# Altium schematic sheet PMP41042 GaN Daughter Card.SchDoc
size 431 x 279 mm; PageSetup: Record=PageOptions¦CenterHorizontal=True¦CenterVertical=True¦PrintScale=1.00¦XCorrection=1.00¦YCorrection=1.00¦PrintKind=0¦BorderSize=5000000¦LeftOffset=0¦BottomOffset=0¦Orientation=2¦PaperLength=1000¦PaperWidth=1000¦Scale=100¦PaperSource=15¦PrintQuality=600¦MediaType=1¦DitherType=10¦PaperKind=Letter¦PrintScaleMode=1
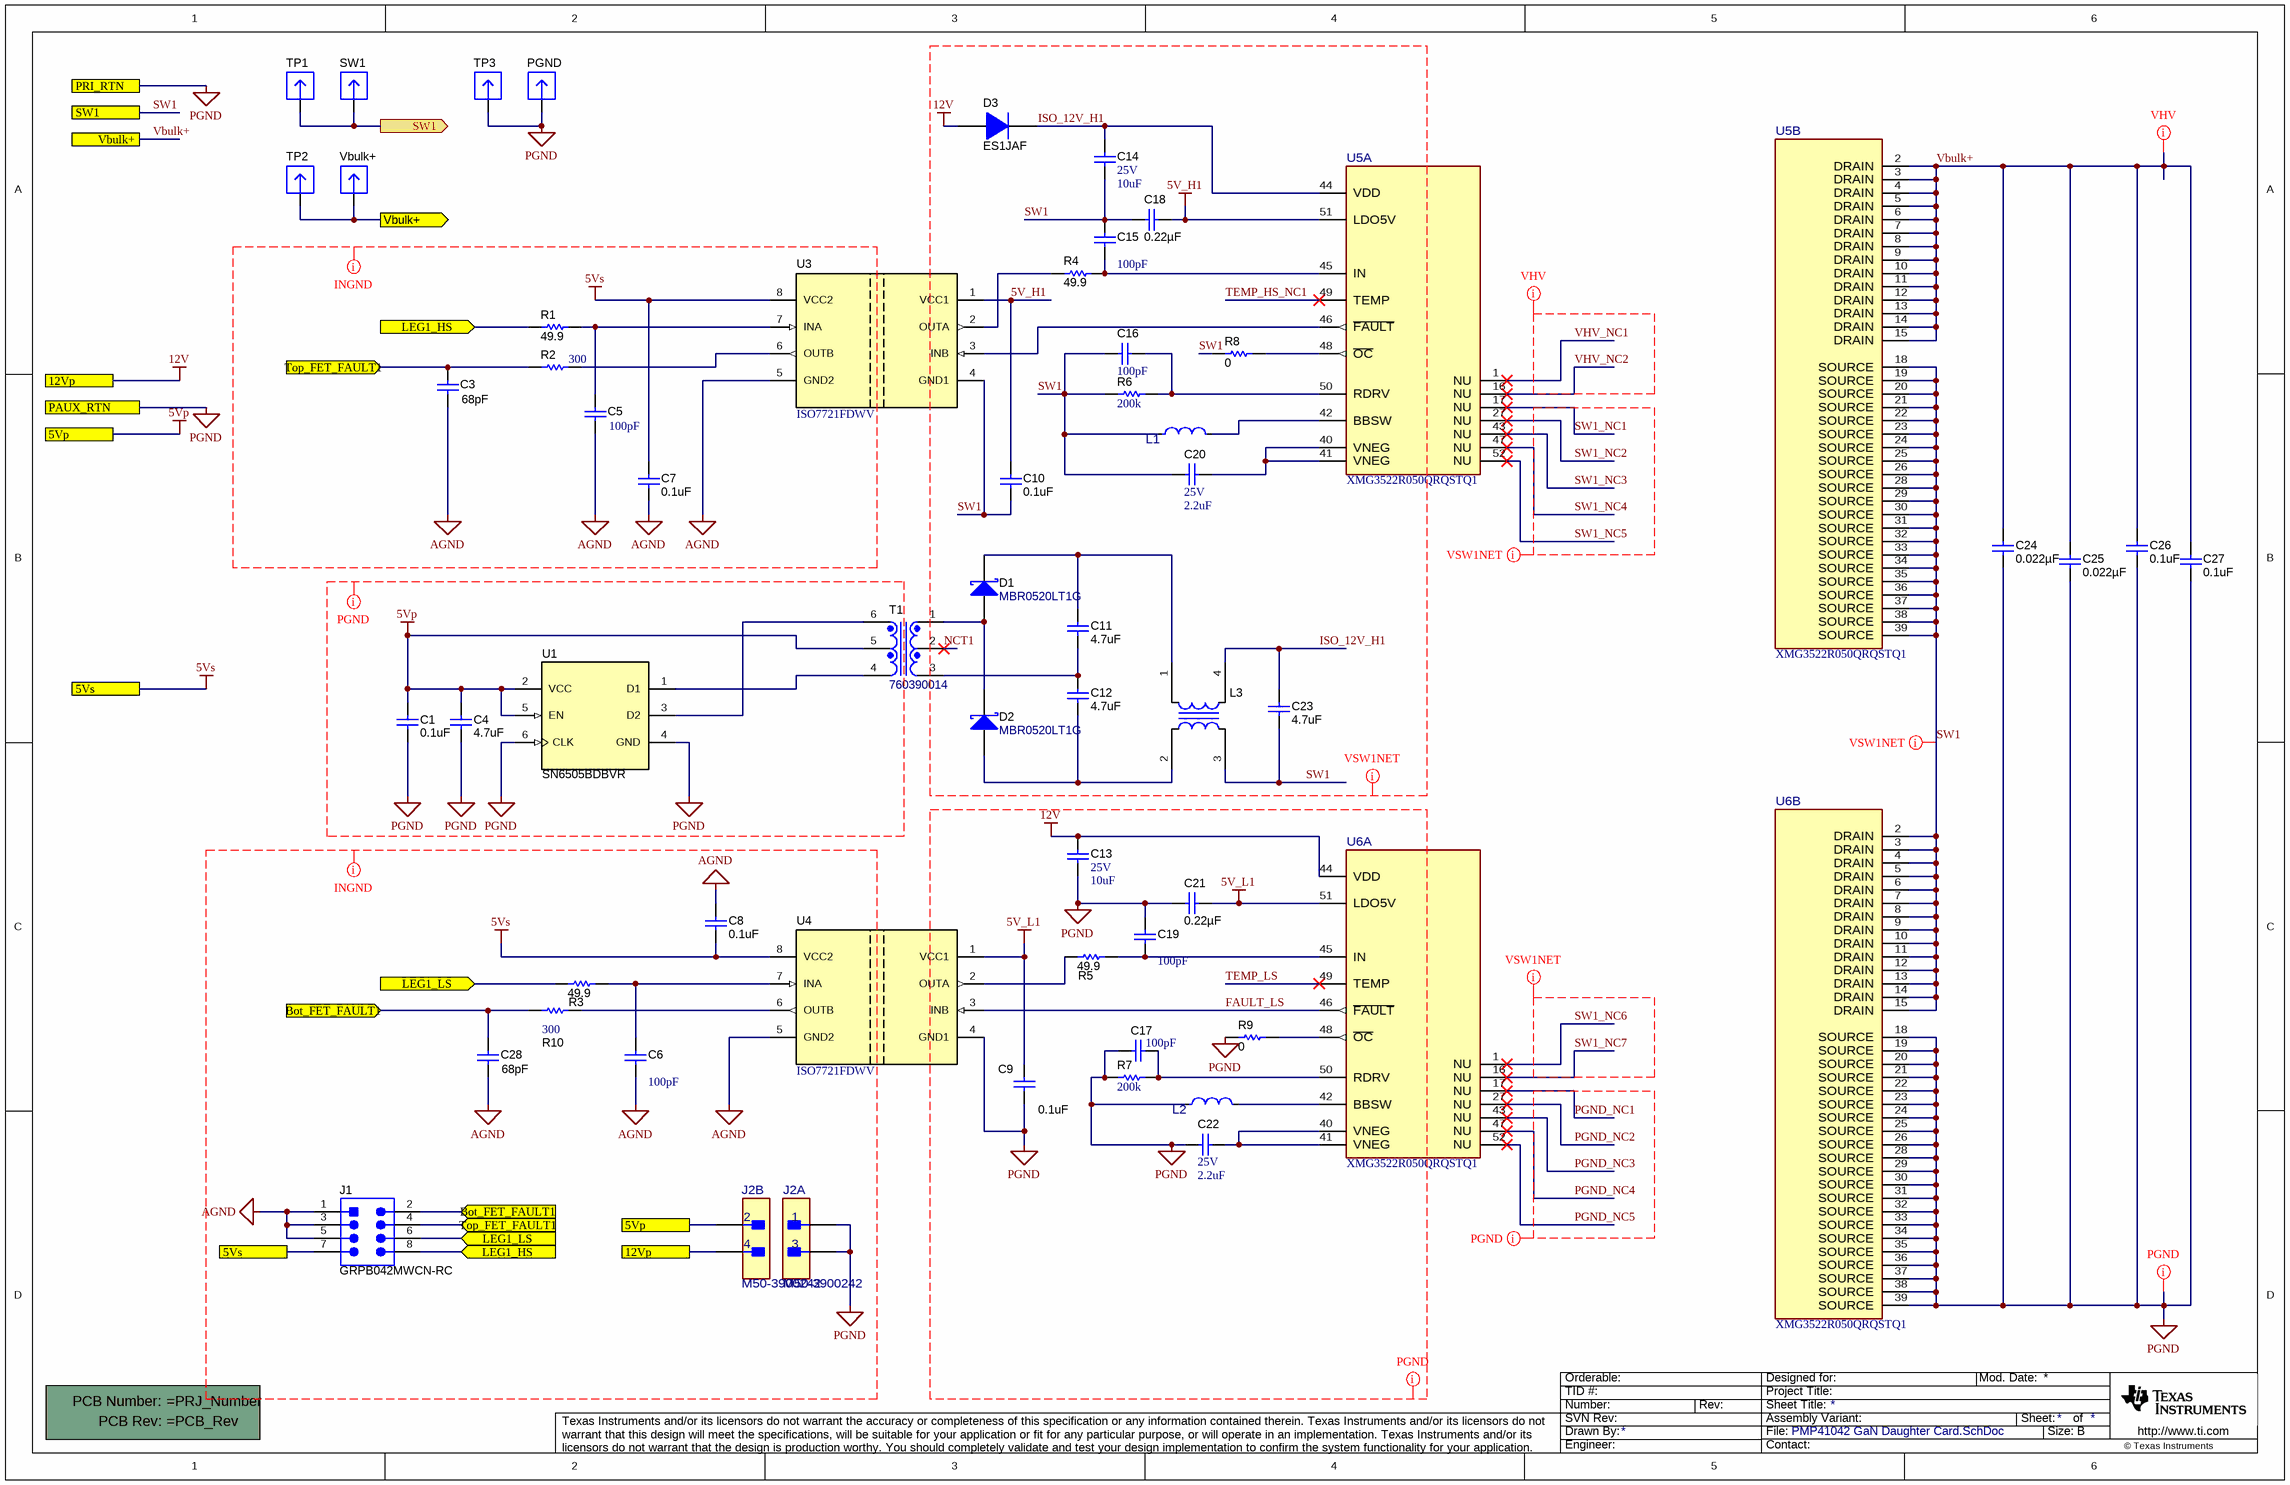
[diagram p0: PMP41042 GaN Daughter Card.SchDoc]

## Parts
!PCB1  Printed Circuit Board  (value not drawn)  (mechanical)
C1  ValueDisplayed: 0.1uF  [0402]  (hidden comment: C1005X7R1H104K050BB)
C3  ValueDisplayed: 68pF  [0402L]  (hidden comment: C1005C0G1H680J050BA)
C4  ValueDisplayed: 4.7uF  [0805_HV]  (hidden comment: GCM21BR71C475KA73L)
C5  ValueDisplayed: 100pF  [0402L]  (hidden comment: 04025A101FAT2A)
C6  ValueDisplayed: 100pF  [0402L]  (hidden comment: 04025A101FAT2A)
C7  ValueDisplayed: 0.1uF  [0402L]  (hidden comment: C1005X7R1H104K050BB)
C8  ValueDisplayed: 0.1uF  [0402L]  (hidden comment: C1005X7R1H104K050BB)
C9  ValueDisplayed: 0.1uF  [0402L]  (hidden comment: C1005X7R1H104K050BB)
C10  ValueDisplayed: 0.1uF  [0402L]  (hidden comment: C1005X7R1H104K050BB)
C11  ValueDisplayed: 4.7uF  [0603]  (hidden comment: C1608X5R1V475K080AC)
C12  ValueDisplayed: 4.7uF  [0603]  (hidden comment: C1608X5R1V475K080AC)
C13  VDC_V: 25V  ValueDisplayed: 10uF  [1206_190]  (hidden comment: C3216X7R1E106M160AE)
C14  VDC_V: 25V  ValueDisplayed: 10uF  [1206_190]  (hidden comment: C3216X7R1E106M160AE)
C15  ValueDisplayed: 100pF  [0402L]  (hidden comment: 04025A101FAT2A)
C16  ValueDisplayed: 100pF  [0402L]  (hidden comment: 04025A101FAT2A)
C17  ValueDisplayed: 100pF  [0402L]  (hidden comment: 04025A101FAT2A)
C18  ValueDisplayed: 0.22µF  [0402L]  (hidden comment: CL05B224KO5NNNC)
C19  ValueDisplayed: 100pF  [0402L]  (hidden comment: 04025A101FAT2A)
C20  VDC_V: 25V  ValueDisplayed: 2.2uF  [0402L]  (hidden comment: GRT155R61E225KE13D)
C21  ValueDisplayed: 0.22µF  [0402L]  (hidden comment: CL05B224KO5NNNC)
C22  VDC_V: 25V  ValueDisplayed: 2.2uF  [0402L]  (hidden comment: GRT155R61E225KE13D)
C23  ValueDisplayed: 4.7uF  [0603]  (hidden comment: C1608X5R1V475K080AC)
C24  ValueDisplayed: 0.022µF  [1206_190]  (hidden comment: C1206C223KDRACTU)
C25  ValueDisplayed: 0.022µF  [1206_190]  (hidden comment: C1206C223KDRACTU)
C26  ValueDisplayed: 0.1uF  [1812_254]  (hidden comment: C1812W104KDRACTU)
C27  ValueDisplayed: 0.1uF  [1812_254]  (hidden comment: C1812W104KDRACTU)
C28  ValueDisplayed: 68pF  [0402L]  (hidden comment: C1005C0G1H680J050BA)
D1  MBR0520LT1G  [SOD-123]
D2  MBR0520LT1G  [SOD-123]
D3  ES1JAF  [SMAF]
J1  GRPB042MWCN-RC  [Sullins_GRPB042MWCN]
J2  M50-3900242  [FP-M50-3900242_HDR4-MFG]  (parts A,B of 2)
L1  SDEM20161T-4R7MS  [FP-SDEM20161T-4R7MS_SMD2-MFG]  (value not drawn)
L2  SDEM20161T-4R7MS  [FP-SDEM20161T-4R7MS_SMD2-MFG]  (value not drawn)
L3  ACM2520-601-2P-T002  [TDK_ACM2520-2P]  (value not drawn)
PGND  3621-0-32-15-00-00-08-0  [Mill-Max_3621-0-32-xx-00-00-08-0]  (value not drawn)
R1  ValueDisplayed: 49.9  [0402L]  (hidden comment: RC0402FR-0749R9L)
R2  ValueDisplayed: 300  [0402L]  (hidden comment: CRCW0402300RJNED)
R3  ValueDisplayed: 49.9  [0402L]  (hidden comment: RC0402FR-0749R9L)
R4  ValueDisplayed: 49.9  [0402L]  (hidden comment: RC0402FR-0749R9L)
R5  ValueDisplayed: 49.9  [0402L]  (hidden comment: RC0402FR-0749R9L)
R6  ValueDisplayed: 200k  [0402L]  (hidden comment: ERJ-2RKF2003X)
R7  ValueDisplayed: 200k  [0402L]  (hidden comment: ERJ-2RKF2003X)
R8  ValueDisplayed: 0  [0402L]  (hidden comment: ERJ-2GE0R00X)  (no BOM)
R9  ValueDisplayed: 0  [0402L]  (hidden comment: ERJ-2GE0R00X)  (no BOM)
R10  ValueDisplayed: 300  [0402L]  (hidden comment: CRCW0402300RJNED)
SW1  3621-0-32-15-00-00-08-0  [Mill-Max_3621-0-32-xx-00-00-08-0]  (value not drawn)
T1  760390014  [Wurth_760390013]
TP1  3621-0-32-15-00-00-08-0  [Mill-Max_3621-0-32-xx-00-00-08-0]  (value not drawn)
TP2  3621-0-32-15-00-00-08-0  [Mill-Max_3621-0-32-xx-00-00-08-0]  (value not drawn)
TP3  3621-0-32-15-00-00-08-0  [Mill-Max_3621-0-32-xx-00-00-08-0]  (value not drawn)
U1  SN6505BDBVR  [DBV0006A_N]
U3  ISO7721FDWV  [DWV0008A]
U4  ISO7721FDWV  [DWV0008A]
U5  PartNumber: XMG3522R050QRQSTQ1  [RQS0052A-MFG]  (hidden comment: XMG3522R030QRQSTQ1)  (parts A,B of 2)
U6  PartNumber: XMG3522R050QRQSTQ1  [RQS0052A-MFG]  (hidden comment: XMG3522R030QRQSTQ1)  (parts A,B of 2)
Vbulk+  3621-0-32-15-00-00-08-0  [Mill-Max_3621-0-32-xx-00-00-08-0]  (value not drawn)

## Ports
5Vp, 5Vs, 12Vp, Bot_FET_FAULT1 (in), LEG1_HS (in), LEG1_LS (in), PAUX_RTN, PRI_RTN, SW1, SW1 (out), Top_FET_FAULT1 (in), Vbulk+, Vbulk+ (out)

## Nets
5V_H1: C10.1 C18.2 U3.1(VCC1) U5.51(LDO5V)
5V_L1: C9.2 C21.2 U4.1(VCC1) U6.51(LDO5V)
5Vp: C1.1 C4.1 J2.2 T1.5 U1.2(VCC) U1.5(EN) ; port 5Vp
5Vs: C7.1 C8.2 J1.7 U3.8(VCC2) U4.8(VCC2) ; port 5Vs
12V: C13.1 D3.2(A) J2.4 U6.44(VDD) ; port 12Vp
AGND: C3.2 C5.2 C6.2 C7.2 C8.1 C28.2 J1.1 J1.3 J1.5 U3.5(GND2) U4.5(GND2)
PGND: C1.2 C4.2 C9.1 C13.2 C17.1 C19.1 C21.1 C22.2 C24.2 C25.2 C26.2 C27.2 J2.1 J2.3 L2.1 PGND.1 R7.1 R9.1 TP3.1 U1.4(GND) U1.6(CLK) U4.4(GND1) U6.18(SOURCE) U6.19(SOURCE) U6.20(SOURCE) U6.21(SOURCE) U6.22(SOURCE) U6.23(SOURCE) U6.24(SOURCE) U6.25(SOURCE) U6.26(SOURCE) U6.28(SOURCE) U6.29(SOURCE) U6.30(SOURCE) U6.31(SOURCE) U6.32(SOURCE) U6.33(SOURCE) U6.34(SOURCE) U6.35(SOURCE) U6.36(SOURCE) U6.37(SOURCE) U6.38(SOURCE) U6.39(SOURCE) ; port PRI_RTN, port PAUX_RTN
Bot_FET_FAULT1: C28.1 J1.2 R10.1 ; port Bot_FET_FAULT1
FAULT_LS: U4.3(INB) U6.46(~{FAULT})
ISO_12V_H1: C14.1 C23.1 D3.1(K) L3.4 U5.44(VDD)
LEG1_HS: J1.8 R1.1 ; port LEG1_HS
LEG1_LS: J1.6 R3.1 ; port LEG1_LS
NCT1: T1.2
PGND_NC1: U6.17(NU)
PGND_NC2: U6.27(NU)
PGND_NC3: U6.43(NU)
PGND_NC4: U6.47(NU)
PGND_NC5: U6.52(NU)
SW1: C10.2 C14.2 C15.1 C16.1 C18.1 C20.2 C23.2 L1.1 L3.3 R6.1 R8.1 SW1.1 TP1.1 U3.4(GND1) U5.18(SOURCE) U5.19(SOURCE) U5.20(SOURCE) U5.21(SOURCE) U5.22(SOURCE) U5.23(SOURCE) U5.24(SOURCE) U5.25(SOURCE) U5.26(SOURCE) U5.28(SOURCE) U5.29(SOURCE) U5.30(SOURCE) U5.31(SOURCE) U5.32(SOURCE) U5.33(SOURCE) U5.34(SOURCE) U5.35(SOURCE) U5.36(SOURCE) U5.37(SOURCE) U5.38(SOURCE) U5.39(SOURCE) U6.2(DRAIN) U6.3(DRAIN) U6.4(DRAIN) U6.5(DRAIN) U6.6(DRAIN) U6.7(DRAIN) U6.8(DRAIN) U6.9(DRAIN) U6.10(DRAIN) U6.11(DRAIN) U6.12(DRAIN) U6.13(DRAIN) U6.14(DRAIN) U6.15(DRAIN) ; port SW1
SW1_NC1: U5.17(NU)
SW1_NC2: U5.27(NU)
SW1_NC3: U5.43(NU)
SW1_NC4: U5.47(NU)
SW1_NC5: U5.52(NU)
SW1_NC6: U6.1(NU)
SW1_NC7: U6.16(NU)
TEMP_HS_NC1: U5.49(TEMP)
TEMP_LS: U6.49(TEMP)
Top_FET_FAULT1: C3.1 J1.4 R2.1 ; port Top_FET_FAULT1
Vbulk+: C24.1 C25.1 C26.1 C27.1 TP2.1 U5.2(DRAIN) U5.3(DRAIN) U5.4(DRAIN) U5.5(DRAIN) U5.6(DRAIN) U5.7(DRAIN) U5.8(DRAIN) U5.9(DRAIN) U5.10(DRAIN) U5.11(DRAIN) U5.12(DRAIN) U5.13(DRAIN) U5.14(DRAIN) U5.15(DRAIN) Vbulk+.1 ; port Vbulk+
VHV_NC1: U5.1(NU)
VHV_NC2: U5.16(NU)
NetC5_1: C5.1 R1.2 U3.7(INA)
NetC6_1: C6.1 R3.2 U4.7(INA)
NetC11_1: C11.1 D1.1(K) L3.1
NetC11_2: C11.2 C12.1 T1.3
NetC12_2: C12.2 D2.2(A) L3.2
NetC15_2: C15.2 R4.1 U5.45(IN)
NetC16_2: C16.2 R6.2 U5.50(RDRV)
NetC17_2: C17.2 R7.2 U6.50(RDRV)
NetC19_2: C19.2 R5.2 U6.45(IN)
NetC20_1: C20.1 U5.40(VNEG) U5.41(VNEG)
NetC22_1: C22.1 U6.40(VNEG) U6.41(VNEG)
NetD1_2: D1.2(A) D2.1(K) T1.1
NetL1_2: L1.2 U5.42(BBSW)
NetL2_2: L2.2 U6.42(BBSW)
NetR2_2: R2.2 U3.6(OUTB)
NetR4_2: R4.2 U3.2(OUTA)
NetR5_1: R5.1 U4.2(OUTA)
NetR8_2: R8.2 U5.48(~{OC})
NetR9_2: R9.2 U6.48(~{OC})
NetR10_2: R10.2 U4.6(OUTB)
NetT1_4: T1.4 U1.1(D1)
NetT1_6: T1.6 U1.3(D2)
NetU3_3: U3.3(INB) U5.46(~{FAULT})

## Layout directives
net class INGND: 5Vs, AGND, PGND
net class VSW1NET: 5V_H1, 12V, ISO_12V_H1, NCT1, SW1, SW1_NC1, SW1_NC2, SW1_NC3, SW1_NC4, SW1_NC5, SW1_NC6, SW1_NC7, TEMP_HS_NC1
net class PGND: 5V_L1, 5Vp, 12V, FAULT_LS, PGND, PGND_NC1, PGND_NC2, PGND_NC3, PGND_NC4, PGND_NC5, TEMP_LS
net class VHV: Vbulk+, VHV_NC1, VHV_NC2

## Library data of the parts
!PCB1 = CMP-0003618-2: Manufacturer: Any
C1 = CMP-0006297-2: CAP, CERM, 0.1 uF, 50 V, +/- 10%, X7R, 0402; Manufacturer: TDK; Alternate PartNumber: 885012205037; Alternate Manufacturer: Wurth Elektronik; Polarized: N; CompType: Capacitor; Value: 0.1uF; U/M: EA; Cap_F: 100nF; ESR_ohm: 0.039064; Value1: 0.039064 ohm; VDC_V: 50V; IRMS_A: 8.14669dA; TaMin_C: -55°C; TaMax_C: 125°C; SizeArea_mm2: 0.5; SizeAreaWB_mm2: 3; SizeX_mm: 1; SizeZ_mm: 0.6; AEC Category: Q200
C3 C28 = CMP-0006251-2: CAP, CERM, 68 pF, 50 V, +/- 5%, C0G/NP0, 0402; Manufacturer: TDK; Alternate Manufacturer: Murata; Alternate PartNumber: GRM1555C1H680JA01D; TaMin_C: -55°C; Polarized: N; SizeAreaWB_mm2: 3; Value1: Unknown; U/M: EA; Value: 68pF; TaMax_C: 125°C; SizeZ_mm: 0.6; SizeX_mm: 1; SizeY_mm: 0.5; Cap_Case: 0402; Value2: 50V; AEC Category: Q200
C4 = CMP-0008020-2: CAP, CERM, 4.7 uF, 16 V, +/- 10%, X7R, AEC-Q200 Grade 1, 0805; Manufacturer: MuRata; TaMin_C: -55°C; Polarized: N; SizeAreaWB_mm2: 6.75; Value1: Unknown; U/M: EA; Value: 4.7uF; TaMax_C: 125°C; SizeZ_mm: 1.45; SizeX_mm: 2; SizeY_mm: 1.25; Cap_Case: 0805; Value2: 16V; SizeArea_mm2: 2.5; AEC Qualified: Y; Cap_F: 4.7µF; AEC Grade: 1; AEC Category: Q200
C5 C6 C15-C17 C19 = CMP-0006196-2: CAP, CERM, 100 pF, 50 V, +/- 1%, C0G/NP0, 0402; Manufacturer: AVX; TaMin_C: -55°C; Polarized: N; SizeAreaWB_mm2: 3; Value1: Unknown; U/M: EA; Value: 100pF; TaMax_C: 125°C; SizeZ_mm: 0.6; SizeX_mm: 1; SizeY_mm: 0.5; Cap_Case: 0402; Value2: 50V; AEC Category: Q200
C7-C10 = CMP-0006297-2: CAP, CERM, 0.1 uF, 50 V, +/- 10%, X7R, 0402; Manufacturer: TDK; Alternate PartNumber: 885012205037; Alternate Manufacturer: Wurth Elektronik; Polarized: N; Value: 0.1uF; U/M: EA; Cap_F: 100nF; ESR_ohm: 0.039064; Value1: 0.039064 ohm; VDC_V: 50V; IRMS_A: 8.14669dA; TaMin_C: -55°C; TaMax_C: 125°C; Cap_Case: 0402; SizeArea_mm2: 0.5; SizeAreaWB_mm2: 3; SizeX_mm: 1; SizeZ_mm: 0.6; AEC Category: Q200
C11 C12 = CMP-0007022-5: CAP, CERM, 4.7 uF, 35 V, +/- 10%, X5R, 0603; Manufacturer: TDK; TaMin_C: -55°C; ESR_ohm: 3.728m; Polarized: N; SizeAreaWB_mm2: 4.68; Value1: 0.003728 ohm; U/M: EA; Value: 4.7uF; TaMax_C: 85°C; SizeZ_mm: 1; SizeX_mm: 1.6; SizeY_mm: 0.8; Value2: 35V; SizeArea_mm2: 1.28; CompType: Capacitor; Cap_F: 4.7µF; IRMS_A: 2.69359A; AEC Category: Q200
C13 C14 = CMP-0008692-2: CAP, CERM, 10 uF, 25 V, +/- 20%, X7R, 1206_190; Manufacturer: TDK; TaMin_C: -55°C; Polarized: N; SizeAreaWB_mm2: 10.92; Value1: Unknown; U/M: EA; Value: 10uF; TaMax_C: 125°C; SizeZ_mm: 1.9; SizeX_mm: 3.2; SizeY_mm: 1.6; Cap_Case: 1206; SizeArea_mm2: 5.12; Cap_F: 10µF; AEC Category: Q200
C18 C21 = CMP-0860563-1: CAP, CERM, 0.22 µF, 16 V,+/- 10%, X7R, 0402; Manufacturer: Samsung Electro-Mechanics; SizeX_mm: 1; Cap_Case: 0402; Green_REACh: Incomplete; TaMin_C: -55°C; SizeArea_mm2: 0.5; TaMax_C: 125°C; U/M: EA; Green_Lifecycle: Active; SizeAreaWB_mm2: 3; VDC_V: 16V; AEC Qualified: N; SizeZ_mm: 0.6; AEC Category: Q200; Cap_F: 220nF; Value: 0.22uF
C20 C22 = CMP-0006716-2: CAP, CERM, 2.2 uF, 25 V, +/- 10%, X5R, AEC-Q200 Grade 3, 0402; Manufacturer: MuRata; TaMin_C: -55°C; Polarized: N; SizeAreaWB_mm2: 3; Value1: Unknown; U/M: EA; Value: 2.2uF; TaMax_C: 85°C; SizeZ_mm: 0.6; SizeX_mm: 1; SizeY_mm: 0.5; Cap_Case: 0402; AEC Qualified: Y; Cap_F: 2.2µF; AEC Category: Q200
C23 = CMP-0007022-5: CAP, CERM, 4.7 uF, 35 V, +/- 10%, X5R, 0603; Manufacturer: TDK; TaMin_C: -55°C; ESR_ohm: 3.728m; Polarized: N; SizeAreaWB_mm2: 4.68; Value1: 0.003728 ohm; U/M: EA; Value: 4.7uF; TaMax_C: 85°C; SizeZ_mm: 1; SizeX_mm: 1.6; SizeY_mm: 0.8; Value2: 35V; SizeArea_mm2: 1.28; Cap_F: 4.7µF; IRMS_A: 2.69359A; AEC Category: Q200
C24 C25 = CMP-0084048-1: CAP, CERM, 0.022 µF, 1000 V,+/- 10%, X7R, AEC-Q200 Grade 1, 1206; Manufacturer: Kemet; Polarized: N; CompType: Capacitor; Value: 0.022uF; U/M: EA; Cap_F: 22nF; VDC_V: 1kV; Value2: 1000V; TaMin_C: -55°C; TaMax_C: 125°C; Cap_Case: 1206; SizeArea_mm2: 5.12; SizeAreaWB_mm2: 10.92; SizeX_mm: 3.2; SizeY_mm: 1.6; SizeZ_mm: 1.9; AEC Category: Q200; AEC Qualified: Y; AEC Grade: 1
C26 C27 = CMP-0009326-2: CAP, CERM, 0.1 uF, 1000 V, +/- 10%, X7R, 1812; Manufacturer: Kemet; Polarized: N; Value: 0.1uF; U/M: EA; Cap_F: 100nF; Value1: Unknown; VDC_V: 1kV; Value2: 1000V; TaMin_C: -55°C; TaMax_C: 125°C; Cap_Case: 1812; AEC Category: Q200; SizeArea_mm2: 14.4; SizeAreaWB_mm2: 23.1; SizeX_mm: 4.5; SizeY_mm: 3.2; SizeZ_mm: 2.54
D1 D2 = CMP-0028524-2: Diode, Schottky, 20 V, 0.5 A, SOD-123; Manufacturer: ON Semiconductor; Green_REACh: Passed; TJmax_C: 125°C; Value1: 0.5A; SizeZ_mm: 1.35; Value2: 0.385V; Vf_V: 385mV; AEC Category: Q101; SizeY_mm: 1.7; Value: 20V; Io_A: 500mA; SizeX_mm: 3.85; Green_Lifecycle: Active; RJC_CperW: 150; SizeAreaWB_mm2: 13.095; SizeArea_mm2: 6.545
D3 = CMP-0029162-2: Diode, Ultrafast, 600 V, 1 A, AEC-Q101, SMAF; Manufacturer: Fairchild Semiconductor; TJmax_C: 150°C; Green_Lifecycle: Not Set; Green_REACh: Incomplete; Value: 600V; SizeY_mm: 2.5; Io_A: 1A; AEC Category: Q101; SizeArea_mm2: 11.75; SizeX_mm: 4.7; AEC Qualified: Y; SizeZ_mm: 1; SizeAreaWB_mm2: 19.95; Value2: 1.7V
J1 = CMP-0086278-1: Header, 1.27mm, 4x2, Gold, R/A, TH; Manufacturer: Sullins Connector Solutions; Current_A: 1A; Shrouded: N; Pitch_mm: 1.27; Voltage_V: 500V; Gender: Male; Row_Count: 2
J2 = CMP-0097643-1: Manufacturer: Harwin; SizeZ_mm: 3.55mm; Is Female: no; Conn Orientation: Right Angle; Current_A: 1A; ContactFinish: Gold,Nickel; Row_Count: 2; DUT-Pitch_mm: 1.27mm; Conn Gender: Male
L1 L2 = CMP-0089347-1: 4.7µH Unshielded Inductor 1.1A 426mOhm Max 0806 (2016 Metric); Manufacturer: Cyntec; AEC Qualified: No; Material: Metal Dust; Isat: 1.26A; Test Frequency: 1MHz; DCR_ohm: 0.426; SizeZ_mm: 1mm; Tolerance_%: 20%
L3 = CMP-0013161-2: Coupled inductor, 0.2 A, 0.45 ohm, SMD; Manufacturer: TDK; SizeAreaWB_mm2: 10.5; DCR_ohm: 0.45; SizeZ_mm: 1.3; SizeX_mm: 2.5; SizeY_mm: 2; SizeArea_mm2: 5
PGND SW1 TP1-TP3 Vbulk+ = CMP-0082316-1: Manufacturer: Mill-Max; CompType: PCB Pin; ContactFinish: Gold; Gender: Male; Row_Count: 1
R1 R3 R5 = CMP-0026738-1: RES, 49.9, 1%, 0.063 W, 0402; Manufacturer: Yageo America; Value: 49.9; Value_Code: 49R9; Power_W: 63mW; Value2: 0.063W; VDC_V: 50V; TempCo: 100 ppm/C; EIA_Code: E96; U/M: EA; AEC Category: Q200; AEC Qualified: N; SizeArea_mm2: 0.5; SizeX_mm: 1; SizeZ_mm: 0.6
R2 R10 = CMP-0026902-3: RES, 300, 5%, 0.063 W, AEC-Q200 Grade 0, 0402; Manufacturer: Vishay-Dale; Power_W: 63mW; TempCo: 200 ppm/C; Value_Code: 300R; Value: 300; EIA_Code: E24; SizeX_mm: 1; SizeY_mm: 0.5; SizeZ_mm: 0.6; Value2: 0.063W; AEC Qualified: Y; VDC_V: 50V; AEC Category: Q200; AEC Grade: 0
R4 = CMP-0026738-1: RES, 49.9, 1%, 0.063 W, 0402; Manufacturer: Yageo America; CompType: Resistor; Value: 49.9; Value_Code: 49R9; Power_W: 63mW; Value2: 0.063W; VDC_V: 50V; TempCo: 100 ppm/C; EIA_Code: E96; U/M: EA; AEC Category: Q200; AEC Qualified: N; SizeArea_mm2: 0.5; SizeX_mm: 1; SizeZ_mm: 0.6
R6 R7 = CMP-0026677-1: RES, 200 k, 1%, 0.1 W, 0402; Manufacturer: Panasonic; Power_W: 100mW; TempCo: 100 ppm/C; U/M: EA; Value: 200k; EIA_Code: E96; SizeX_mm: 1; SizeY_mm: 0.5; SizeZ_mm: 0.6; Value2: 0.1W; VDC_V: 50V; AEC Category: Q200
R8 R9 = CMP-0026992-3: RES, 0, 5%, 0.1 W, AEC-Q200 Grade 0, 0402; Manufacturer: Panasonic; Power_W: 100mW; TempCo: 600 ppm/C; Value_Code: 0000; Value: 0; EIA_Code: E24; SizeX_mm: 1; SizeY_mm: 0.5; SizeZ_mm: 0.6; Value2: 0.1W; AEC Qualified: Y; VDC_V: 50V; AEC Category: Q200; SizeAreaWB_mm2: 3
T1 = CMP-0030718-1: Transformer, 475uH, SMT; Manufacturer: Wurth Elektronik; DCR_ohm: 0.31; Lp: 475; Ind_H: 475µH
U1 = CMP-0076095-1: Low-Noise 1 A, 420 kHz Transformer Driver, DBV0006A (SOT-23-6); Alternate PartNumber: SN6505BDBVT; Manufacturer: Texas Instruments; SizeArea_mm2: 8.12; SizeAreaWB_mm2: 14.82; SizeX_mm: 2.8; SizeY_mm: 2.9; SizeZ_mm: 1.45; CompType: IC; U/M: EA; Green_Lifecycle: Active; Green_REACh: Passed
U3 U4 = CMP-0085676-1: High Speed, Robust EMC Reinforced Dual-Channel Digital Isolator, DWV0008A (SOIC-8); Alternate Manufacturer: Texas Instruments; Alternate PartNumber: ISO7721FDWVR; Rating: Catalog; SizeX_mm: 11.5; SizeArea_mm2: 67.275; CompType: IC; AEC Qualified: N; SizeY_mm: 5.85; SizeAreaWB_mm2: 105.975; SizeZ_mm: 2.8; AEC Category: Q200
U5 U6 = CMP-0092112-1: 650-V 30-mΩ GaN FET with Integrated Driver, Protection, and Temperature Reporting; Manufacturer: Texas Instruments; Number Of Drivers: 1; Max Supply Voltage: 18V; Rise Time: 2.5ns; Output Voltage: 520V; AEC Grade: Grade 1; SizeZ_mm: 1mm; TJmax_C: +125°C; Standoff Height: 0mm; Min Supply Voltage: 7.5V; Turn Off Delay Time: 6ns; Turn On Delay Time: 5ns; AEC Qualified: Yes; Nominal Supply Current: 700-16000uA; Fall Time: 23ns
